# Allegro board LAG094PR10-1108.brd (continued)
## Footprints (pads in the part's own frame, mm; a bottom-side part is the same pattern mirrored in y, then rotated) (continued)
ACES_50673-0120N-001_12P-T
  oval 0.61x1.499 smd: 1(0,0) 3(-1,0) 5(-2,0) 7(-3,0) 9(-4,0) 11(-5,0) 13(-6,0) 15(-7,0) 17(-8,0) 19(-9,0) 21(-10,0) 23(-11,0)
  oval 0.61x1.194 smd: 2(0,2.85) 4(-1,2.85) 6(-2,2.85) 8(-3,2.85) 10(-4,2.85) 12(-5,2.85) 14(-6,2.85) 16(-7,2.85) 18(-8,2.85) 20(-9,2.85) 22(-10,2.85) 24(-11,2.85)
  rect 1.702x2.311 smd: 25(-13.25,1.425) 26(2.25,1.425)
ACES_51522-00801-001_8P
  oval 0.305x1.295 smd: 1(0,0) 2(0.5,0) 3(1,0) 4(1.5,0) 5(2,0) 6(2.5,0) 7(3,0) 8(3.5,0)
  rect 2.489x1.905 smd: 9(5.65,-3.3) 10(-2.15,-3.3)
ACES_51524-0080N-001_8P
  oval 0.61x1.295 smd: 1(0,0) 2(1,0) 3(2,0) 4(3,0) 5(4,0) 6(5,0) 7(6,0) 8(7,0)
  rect 2.489x2.21 smd: 9(10,-3.05) 10(-3,-3.05)
ACES_51524-0160N-001_16P
  oval 0.61x1.295 smd: 1(0,0) 2(1,0) 3(2,0) 4(3,0) 5(4,0) 6(5,0) 7(6,0) 8(7,0) 9(8,0) 10(9,0) 11(10,0) 12(11,0) 13(12,0) 14(13,0) 15(14,0) 16(15,0)
  rect 2.159x2.21 smd: 17(-2.825,-3.05) 18(17.825,-3.05)
ACES_51540-04001-P01_40P
  oval 0.305x1.092 smd: 1(0,0) 2(0.5,0) 3(1,0) 4(1.5,0) 5(2,0) 6(2.5,0) 7(3,0) 8(3.5,0) 9(4,0) 10(4.5,0) 11(5,0) 12(5.5,0) 13(6,0) 14(6.5,0) 15(7,0) 16(7.5,0) 17(8,0) 18(8.5,0) 19(9,0) 20(9.5,0) 21(10,0) 22(10.5,0) 23(11,0) 24(11.5,0) 25(12,0) 26(12.5,0) 27(13,0) 28(13.5,0) 29(14,0) 30(14.5,0) 31(15,0) 32(15.5,0) 33(16,0) 34(16.5,0) 35(17,0) 36(17.5,0) 37(18,0) 38(18.5,0) 39(19,0) 40(19.5,0)
  rect 0.787x2.489 smd: 41(21.2,-3.6) 42(-1.7,-3.6)
ACES_51575-00401-001_4P
  oval 0.406x0.838 smd: 1(0,0) 2(1,0) 3(2,0) 4(3,0)
  rect 0.787x2.007 smd: 5(-2.2,-3.175) 6(5.2,-3.175)
ACES_51625-01201-001_12P
  oval 0.305x1.092 smd: 1(0,0) 2(0.5,0) 3(1,0) 4(1.5,0) 5(2,0) 6(2.5,0) 7(3,0) 8(3.5,0) 9(4,0) 10(4.5,0) 11(5,0) 12(5.5,0)
  rect 0.991x2.489 smd: 13(-1.8,-3.6) 14(7.3,-3.6)
ACON_HMRF6-AK120C_19P-T
  round 0.813 hole 0.559: 1(0,0) 2(0.5,1.55) 3(1,0) 4(1.5,1.55) 5(2,0) 6(2.5,1.55) 7(3,0) 8(3.5,1.55) 9(4,0) 10(4.5,1.55) 11(5,0) 12(5.5,1.55) 13(6,0) 14(6.5,1.55) 15(7,0) 16(7.5,1.55) 17(8,0) 18(8.5,1.55) 19(9,0)
  oval 1.499x2.21 hole 0.889x1.6: 20(11.75,1.7) 21(13.65,-7.75) 22(-4.65,-6.5) 23(-2.75,1.7)
ACON_TARAN-9R1391_9P
  round 0.991 hole 0.711: 1(0,0) 2(-2.5,0) 3(-4.5,0) 4(-7,0) 5(-7.5,-1.5) 6(-5.5,-1.5) 7(-3.5,-1.5) 8(-1.5,-1.5) 9(0.5,-1.5)
  oval 1.397x3.2 hole 0.787x2.591: 10(-11.35,-2.38) 12(4.35,-2.38)
  oval 1.397x2.388 hole 0.787x1.803: 11(-11.35,-9.48) 13(4.35,-9.48)
ALC3204-CG_MQFN40_5X5
  oval 0.889x0.203 smd: 1(0,0) 2(0,-0.4) 3(0,-0.8) 4(0,-1.2) 5(0,-1.6) 6(0,-2) 7(0,-2.4) 8(0,-2.8) 9(0,-3.2) 10(0,-3.6) 21(5.1,-3.6) 22(5.1,-3.2) 23(5.1,-2.8) 24(5.1,-2.4) 25(5.1,-2) 26(5.1,-1.6) 27(5.1,-1.2) 28(5.1,-0.8) 29(5.1,-0.4) 30(5.1,0)
  oval 0.203x0.889 smd: 11(0.75,-4.35) 12(1.15,-4.35) 13(1.55,-4.35) 14(1.95,-4.35) 15(2.35,-4.35) 16(2.75,-4.35) 17(3.15,-4.35) 18(3.55,-4.35) 19(3.95,-4.35) 20(4.35,-4.35) 31(4.35,0.75) 32(3.95,0.75) 33(3.55,0.75) 34(3.15,0.75) 35(2.75,0.75) 36(2.35,0.75) 37(1.95,0.75) 38(1.55,0.75) 39(1.15,0.75) 40(0.75,0.75)
  rect 3.607x3.607 smd: 41(2.55,-1.8)
AON6380_DFN5X6-8-5
  oval 0.508x0.838 smd: 1(0,0) 2(1.27,0) 3(2.54,0) 4(3.81,0)
  custom 1.15x1.15 smd: 5(1.905,3.69)
AON7702L_DFN8-5
  oval 0.406x0.991 smd: 1(0,0) 2(0.66,0) 3(1.32,0) 4(1.98,0)
  custom 0.559x0.559 smd: 5(0.99,2.247)
AONH36334_DFN3X3A8-10
  oval 0.457x0.813 smd: 1(0,0) 2(0.65,0) 3(1.3,0) 4(1.95,0) 5(1.95,3.18) 6(1.3,3.18) 7(0.65,3.18) 8(0,3.18)
  rect 2.388x0.991 smd: 9(0.975,2.025)
  rect 2.388x0.508 smd: 10(0.975,0.92)
AP2302GN-HF_SOT23-3
  oval 1.016x1.524 smd: 1(0,0) 2(0.965,2.083) 3(-0.965,2.083)
AZ1045-04F_DFN2510P10E-10-9
  oval 0.254x0.686 smd: 1(0,0) 2(0.5,0) 4(1.5,0) 5(2,0) 6(2,0.875) 7(1.5,0.875) 8(0.5,0.875) 9(0,0.875)
  oval 0.381x1.549 smd: 3(1,0.437)
AZ5123-02SPR7G_SOT23-3
  oval 1.016x1.524 smd: 1(0,0) 2(0.965,2.083) 3(-0.965,2.083)
AZC199-02SPR7G_SOT23-3
  oval 1.016x1.524 smd: 1(0,0) 2(0.965,2.083) 3(-0.965,2.083)
BAS40C_SOT23-3
  oval 1.016x1.524 smd: 1(0,0) 2(0.965,2.083) 3(-0.965,2.083)
BAT54ATB_SOT523-3
  oval 0.406x0.457 smd: 1(0,0) 2(0.5,1.35) 3(-0.5,1.35)
BAT54C-7-F_SOT23-3
  oval 1.016x1.524 smd: 1(0,0) 2(0.965,2.083) 3(-0.965,2.083)
BAT54CW_SOT323-3
  oval 0.711x0.889 smd: 1(0,0) 2(-0.65,-1.9) 3(0.65,-1.9)
BAV99W_SC70-3
  oval 0.508x0.559 smd: 1(0,0) 2(-0.65,-1.85) 3(0.65,-1.85)
BAW56W_SOT323-3
  oval 0.813x0.914 smd: 1(0,0) 2(0.65,1.6) 3(-0.65,1.6)
BOTH_NS0013LF_16P
  oval 0.762x1.905 smd: 1(0,0) 2(1.27,0) 3(2.54,0) 4(3.81,0) 5(5.08,0) 6(6.35,0) 7(7.62,0) 8(8.89,0) 9(8.89,8.8) 10(7.62,8.8) 11(6.35,8.8) 12(5.08,8.8) 13(3.81,8.8) 14(2.54,8.8) 15(1.27,8.8) 16(0,8.8)
C_0201
  rect 0.381x0.356 smd: 1(0,0) 2(0.584,0)
C_0402
  rect 0.508x0.584 smd: 1(0,0) 2(0.914,0)
C_0603
  rect 0.635x0.889 smd: 1(0,0) 2(1.397,0)
C_0805
  rect 0.813x1.397 smd: 1(0,0) 2(1.702,0)
C_1206
  rect 1.016x1.778 smd: 1(0,0) 2(2.667,0)
C_A
  rect 1.626x1.829 smd: 1(0.389,0) 2(2.989,0)
C_B2
  rect 1.346x2.692 smd: 1(0,0) 2(-2.75,0)
C_D2
  rect 2.388x2.794 smd: 1(0,0) 2(6.4,0)
CH751H-40PT_SOD323-2
  rect 0.711x0.711 smd: 1(0,0) 2(2.33,0)
CK0402101V05_0402-2
  rect 0.508x0.559 smd: 1(0,0) 2(0.92,0)
DDTA144VCA-7-F_SOT23-3
  oval 1.016x1.524 smd: 1(0,0) 2(0.965,2.083) 3(-0.965,2.083)
DMN65D8LW-7_SOT323-3
  oval 0.711x0.889 smd: 1(0,0) 2(-0.65,-1.9) 3(0.65,-1.9)
DMN66D0LDW-7_SOT363-6
  oval 0.432x0.61 smd: 1(0,0) 2(0.65,0) 3(1.3,0) 4(1.3,1.9) 5(0.65,1.9) 6(0,1.9)
EMB04N03H_EDFN5X6-8-5
  oval 0.61x1.27 smd: 1(0,0) 2(1.27,0) 3(2.54,0) 4(3.81,0)
  custom 1.105x1.105 smd: 5(1.905,3.715)
F_1206L150PR
  rect 0.991x1.803 smd: 1(0,0) 2(2.8,0)
F_MF-NSMF050-2
  rect 0.991x1.6 smd: 1(0,0) 2(3,0)
F_SMD1812P150TF-24
  rect 1.778x3.15 smd: 1(0,0) 2(5.23,0)
F_T0603FF1000TM
  rect 0.711x0.991 smd: 1(0,0) 2(1.5,0)
FDV301N-G_SOT23-3
  oval 1.016x1.524 smd: 1(0,0) 2(0.965,2.083) 3(-0.965,2.083)
FH8068003067411-QM_FCBGA_1090P
  round 0.305 smd: A3(-0.784,0) A4(-1.381,0) A6(-1.978,0) A7(-2.752,0) A50(-21.403,0) A51(-22,0) A53(-22.609,0) A54(-23.219,0) AA5(-1.713,8.964) AA7(-2.424,8.964) AA8(-3.136,8.964) AA10(-3.847,8.964) AA12(-4.558,8.964) AA13(-5.269,8.964) AA15(-5.98,8.964) AA17(-6.692,8.964) AA39(-16.937,8.964) AA41(-17.648,8.964) AA43(-18.359,8.964) AA44(-19.071,8.964) AA46(-19.782,8.964) AA48(-20.493,8.964) AA49(-21.204,8.964) AA51(-21.915,8.964) AC5(-1.713,9.917) AC7(-2.424,9.917) AC8(-3.136,9.917) AC10(-3.847,9.917) AC12(-4.558,9.917) AC13(-5.269,9.917) AC15(-5.98,9.917) AC17(-6.692,9.917) AC39(-16.937,9.917) AC41(-17.648,9.917) AC43(-18.359,9.917) AC44(-19.071,9.917) AC46(-19.782,9.917) AC48(-20.493,9.917) AC49(-21.204,9.917) AC51(-21.915,9.917) AE5(-1.713,10.793) AE7(-2.424,10.793) AE8(-3.136,10.793) AE10(-3.847,10.793) AE12(-4.558,10.793) AE13(-5.269,10.793) AE15(-5.98,10.793) AE17(-6.692,10.793) AE39(-16.937,10.793) AE41(-17.648,10.793) AE43(-18.359,10.793) AE44(-19.071,10.793) AE46(-19.782,10.793) AE48(-20.493,10.793) AE49(-21.204,10.793) AE51(-21.915,10.793) AF6(-2.069,11.314) AF8(-2.78,11.314) AF9(-3.491,11.314) AF11(-4.202,11.314) AF12(-4.914,11.314) AF14(-5.625,11.314) AF16(-6.336,11.314) AF40(-17.293,11.314) AF42(-18.004,11.314) AF44(-18.715,11.314) AF45(-19.426,11.314) AF47(-20.137,11.314) AF48(-20.849,11.314) AF50(-21.56,11.314) AG5(-1.713,11.835) AG7(-2.424,11.835) AG8(-3.136,11.835) AG10(-3.847,11.835) AG12(-4.558,11.835) AG13(-5.269,11.835) AG15(-5.98,11.835) AG17(-6.692,11.835) AG39(-16.937,11.835) AG41(-17.648,11.835) AG43(-18.359,11.835) AG44(-19.071,11.835) AG46(-19.782,11.835) AG48(-20.493,11.835) AG49(-21.204,11.835) AG51(-21.915,11.835) AJ5(-1.713,12.711) AJ7(-2.424,12.711) AJ8(-3.136,12.711) AJ10(-3.847,12.711) AJ12(-4.558,12.711) AJ13(-5.269,12.711) AJ15(-5.98,12.711) AJ17(-6.692,12.711) AJ39(-16.937,12.711) AJ41(-17.648,12.711) AJ43(-18.359,12.711) AJ44(-19.071,12.711) AJ46(-19.782,12.711) AJ48(-20.493,12.711) AJ49(-21.204,12.711) AJ51(-21.915,12.711) AL5(-1.713,13.663) AL7(-2.424,13.663) AL8(-3.136,13.663) AL10(-3.847,13.663) AL12(-4.558,13.663) AL13(-5.269,13.663) AL15(-5.98,13.663) AL17(-6.692,13.663) AL39(-16.937,13.663) AL41(-17.648,13.663) AL43(-18.359,13.663) AL44(-19.071,13.663) AL46(-19.782,13.663) AL48(-20.493,13.663) AL49(-21.204,13.663) AL51(-21.915,13.663) AN5(-1.713,14.54) AN7(-2.424,14.54) AN8(-3.136,14.54) AN10(-3.847,14.54) AN12(-4.558,14.54) AN13(-5.269,14.54) AN15(-5.98,14.54) AN17(-6.692,14.54) AN39(-16.937,14.54) AN41(-17.648,14.54) AN43(-18.359,14.54) AN44(-19.071,14.54) AN46(-19.782,14.54) AN48(-20.493,14.54) AN49(-21.204,14.54) AN51(-21.915,14.54) AR5(-1.713,15.226) AR7(-2.424,15.226) AR8(-3.136,15.226) AR10(-3.847,15.226) AR12(-4.558,15.226) AR13(-5.269,15.226) AR15(-5.98,15.226) AR17(-6.692,15.226) AR39(-16.937,15.226) AR41(-17.648,15.226) AR43(-18.359,15.226) AR44(-19.071,15.226) AR46(-19.782,15.226) AR48(-20.493,15.226) AR49(-21.204,15.226) AR51(-21.915,15.226) AU5(-1.713,16.102) AU7(-2.424,16.102) AU8(-3.136,16.102) AU10(-3.847,16.102) AU12(-4.558,16.102) AU13(-5.269,16.102) AU15(-5.98,16.102) AU28(-11.814,16.292) AU41(-17.648,16.102) AU43(-18.359,16.102) AU44(-19.071,16.102) AU46(-19.782,16.102) AU48(-20.493,16.102) AU49(-21.204,16.102) AU51(-21.915,16.102) AV15(-6.15,16.647) AV17(-7.026,16.647) AV19(-7.903,16.647) AV21(-8.589,16.647) AV23(-9.465,16.647) AV25(-10.417,16.647) AV27(-11.294,16.647) AV29(-12.335,16.647) AV31(-13.211,16.647) AV33(-14.164,16.647) AV35(-15.04,16.647) AV37(-15.726,16.647) AV39(-16.602,16.647) AV41(-17.479,16.647) AW5(-1.713,17.054) AW7(-2.424,17.054) AW8(-3.136,17.054) AW10(-3.847,17.054) AW12(-4.558,17.054) AW28(-11.814,17.003) AW44(-19.071,17.054) AW46(-19.782,17.054) AW48(-20.493,17.054) AW49(-21.204,17.054) AW51(-21.915,17.054) AY13(-5.121,17.359) AY15(-6.074,17.359) AY17(-7.026,17.359) AY19(-7.903,17.359) AY21(-8.589,17.359) AY23(-9.465,17.359) AY25(-10.417,17.359) AY27(-11.294,17.359) AY28(-11.814,17.714) AY29(-12.335,17.359) AY31(-13.211,17.359) AY33(-14.164,17.359) AY35(-15.04,17.359) AY37(-15.726,17.359) AY39(-16.602,17.359) AY41(-17.555,17.359) AY43(-18.507,17.359) B2(-0.38,0.38) B55(-23.629,0.44) BA5(-1.713,18.007) BA7(-2.424,18.007) BA8(-3.136,18.007) BA10(-3.847,18.007) BA13(-5.121,18.07) BA15(-6.074,18.07) BA17(-7.026,18.07) BA19(-7.903,18.07) BA21(-8.589,18.07) BA23(-9.465,18.07) BA25(-10.417,18.07) BA27(-11.294,18.07) BA29(-12.335,18.07) BA31(-13.211,18.07) BA33(-14.164,18.07) BA35(-15.04,18.07) BA37(-15.726,18.07) BA39(-16.602,18.07) BA41(-17.555,18.07) BA43(-18.507,18.07) BA46(-19.782,18.007) BA48(-20.493,18.007) BA49(-21.204,18.007) BA51(-21.915,18.007) BB28(-11.814,18.425) BC5(-1.713,18.959) BC7(-2.424,18.959) BC8(-3.136,18.959) BC11(-4.169,18.781) BC13(-5.121,18.781) BC15(-6.074,18.781) BC17(-7.026,18.781) BC19(-7.903,18.781) BC21(-8.589,18.781) BC23(-9.465,18.781) BC25(-10.417,18.781) BC27(-11.294,18.781) BC29(-12.335,18.781) BC31(-13.211,18.781) BC33(-14.164,18.781) BC35(-15.04,18.781) BC37(-15.726,18.781) BC39(-16.602,18.781) BC41(-17.555,18.781) BC43(-18.507,18.781) BC45(-19.46,18.781) BC48(-20.493,18.959) BC49(-21.204,18.959) BC51(-21.915,18.959) BD9(-3.293,19.492) BD11(-4.169,19.492) BD13(-5.121,19.492) BD15(-6.074,19.492) BD17(-7.026,19.492) BD19(-7.903,19.492) BD21(-8.589,19.492) BD23(-9.465,19.492) BD25(-10.417,19.492) BD27(-11.294,19.492) BD28(-11.814,19.137) BD29(-12.335,19.492) BD31(-13.211,19.492) BD33(-14.164,19.492) BD35(-15.04,19.492) BD37(-15.726,19.492) BD39(-16.602,19.492) BD41(-17.555,19.492) BD43(-18.507,19.492) BD45(-19.46,19.492) BD47(-20.336,19.492) BE5(-1.713,19.912) BE7(-2.424,19.912) BE28(-11.814,19.848) BE49(-21.204,19.912) BE51(-21.915,19.912) BF1(0,20.371) BF2(-0.551,20.439) BF9(-3.216,20.203) BF11(-4.169,20.203) BF13(-5.121,20.203) BF15(-6.074,20.203) BF17(-7.026,20.203) BF19(-7.903,20.203) BF21(-8.589,20.203) BF23(-9.465,20.203) BF25(-10.417,20.203) BF27(-11.294,20.203) BF29(-12.335,20.203) BF31(-13.211,20.203) BF33(-14.164,20.203) BF35(-15.04,20.203) BF37(-15.726,20.203) BF39(-16.602,20.203) BF41(-17.555,20.203) BF43(-18.507,20.203) BF45(-19.46,20.203) BF47(-20.412,20.203) BF54(-23.078,20.439) BF55(-23.629,20.371) BG1(0,20.968) BG2(-0.551,20.985) BG4(-1.138,21.011) BG6(-2.264,20.915) BG28(-11.814,20.559) BG50(-21.365,20.915) BG52(-22.49,21.011) BG54(-23.078,20.985) BG55(-23.629,20.968) BH1(0,21.578) BH2(-0.551,21.531) BH5(-1.709,21.529) BH6(-2.261,21.531) BH9(-3.216,20.915) BH11(-4.169,20.915) BH13(-5.121,20.915) BH15(-6.074,20.915) BH17(-7.026,20.915) BH19(-7.903,20.915) BH21(-8.589,20.915) BH23(-9.465,20.915) BH25(-10.417,20.915) BH27(-11.294,20.915) BH29(-12.335,20.915) BH31(-13.211,20.915) BH33(-14.164,20.915) BH35(-15.04,20.915) BH37(-15.726,20.915) BH39(-16.602,20.915) BH41(-17.555,20.915) BH43(-18.507,20.915) BH45(-19.46,20.915) BH47(-20.412,20.915) BH50(-21.367,21.531) BH51(-21.919,21.529) BH54(-23.078,21.531) BH55(-23.629,21.578) BJ2(-0.551,22.077) BJ4(-1.097,22.077) BJ5(-1.643,22.077) BJ6(-2.189,22.077) BJ50(-21.439,22.077) BJ51(-21.985,22.077) BJ52(-22.532,22.077) BJ54(-23.078,22.077) BK1(0,22.187) BK55(-23.629,22.187) BL2(-0.41,22.628) BL3(-1.019,22.628) BL5(-1.629,22.628) BL6(-2.226,22.628) BL50(-21.403,22.628) BL51(-22,22.628) BL53(-22.609,22.628) BL54(-23.219,22.628) C1(0,0.784) C2(-0.551,0.945) C3(-0.945,0.551) C5(-1.491,0.551) C6(-2.037,0.551) C7(-2.583,0.551) C50(-21.439,0.551) C51(-21.985,0.551) C52(-22.532,0.551) C54(-23.078,0.551) D1(0,1.381) D2(-0.551,1.491) D4(-1.122,1.097) D6(-2.164,1.084) D9(-3.293,1.713) D11(-4.169,1.713) D13(-5.121,1.713) D15(-6.074,1.713) D17(-7.026,1.713) D19(-7.903,1.713) D21(-8.589,1.713) D23(-9.465,1.713) D25(-10.417,1.713) D27(-11.294,1.713) D29(-12.335,1.713) D31(-13.211,1.713) D33(-14.164,1.713) D35(-15.04,1.713) D37(-15.726,1.713) D39(-16.602,1.713) D41(-17.555,1.713) D43(-18.507,1.713) D45(-19.46,1.713) D47(-20.412,1.713) D50(-21.367,1.097) D51(-21.919,1.099) D54(-23.078,1.097) D55(-23.629,1.05) E2(-0.551,2.037) E5(-1.656,1.592) E7(-2.74,1.618) E28(-11.814,2.069) E50(-21.365,1.713) E52(-22.49,1.616) E54(-23.078,1.643) E55(-23.629,1.66) F1(0,1.978) F2(-0.551,2.583) F4(-1.122,2.113) F6(-2.164,2.1) F9(-3.293,2.424) F11(-4.169,2.424) F13(-5.121,2.424) F15(-6.074,2.424) F17(-7.026,2.424) F19(-7.903,2.424) F21(-8.589,2.424) F23(-9.465,2.424) F25(-10.417,2.424) F27(-11.294,2.424) F29(-12.335,2.424) F31(-13.211,2.424) F33(-14.164,2.424) F35(-15.04,2.424) F37(-15.726,2.424) F39(-16.602,2.424) F41(-17.555,2.424) F43(-18.507,2.424) F45(-19.46,2.424) F47(-20.412,2.424) F54(-23.078,2.189) F55(-23.629,2.257) G5(-1.656,2.634) G7(-2.74,2.634) G28(-11.814,2.78) G49(-21.204,2.716) G51(-21.915,2.716) H1(0,2.752) H4(-1.122,3.129) H6(-2.164,3.116) H9(-3.293,3.136) H11(-4.169,3.136) H13(-5.121,3.136) H15(-6.074,3.136) H17(-7.026,3.136) H19(-7.903,3.136) H21(-8.589,3.136) H23(-9.465,3.136) H25(-10.417,3.136) H27(-11.294,3.136) H28(-11.814,3.491) H29(-12.335,3.136) H31(-13.211,3.136) H33(-14.164,3.136) H35(-15.04,3.136) H37(-15.726,3.136) H39(-16.602,3.136) H41(-17.555,3.136) H43(-18.507,3.136) H45(-19.46,3.136) H47(-20.336,3.136) J5(-1.713,3.745) J7(-2.424,3.745) J8(-3.136,3.745) J11(-4.169,3.847) J13(-5.121,3.847) J15(-6.074,3.847) J17(-7.026,3.847) J19(-7.903,3.847) J21(-8.589,3.847) J23(-9.465,3.847) J25(-10.417,3.847) J27(-11.294,3.847) J29(-12.335,3.847) J31(-13.211,3.847) J33(-14.164,3.847) J35(-15.04,3.847) J37(-15.726,3.847) J39(-16.602,3.847) J41(-17.555,3.847) J43(-18.507,3.847) J45(-19.46,3.847) J48(-20.493,3.669) J49(-21.204,3.669) J51(-21.915,3.669) K28(-11.814,4.202) L5(-1.713,4.621) L7(-2.424,4.621) L8(-3.136,4.621) L10(-3.847,4.621) L13(-5.121,4.558) L15(-6.074,4.558) L17(-7.026,4.558) L19(-7.903,4.558) L21(-8.589,4.558) L23(-9.465,4.558) L25(-10.417,4.558) L27(-11.294,4.558) L29(-12.335,4.558) L31(-13.211,4.558) L33(-14.164,4.558) L35(-15.04,4.558) L37(-15.726,4.558) L39(-16.602,4.558) L41(-17.555,4.558) L43(-18.507,4.558) L46(-19.782,4.621) L48(-20.493,4.621) L49(-21.204,4.621) L51(-21.915,4.621) M13(-5.121,5.269) M15(-6.074,5.269) M17(-7.026,5.269) M19(-7.903,5.269) M21(-8.589,5.269) M23(-9.465,5.269) M25(-10.417,5.269) M27(-11.294,5.269) M28(-11.814,4.914) M29(-12.335,5.269) M31(-13.211,5.269) M33(-14.164,5.269) M35(-15.04,5.269) M37(-15.726,5.269) M39(-16.602,5.269) M41(-17.555,5.269) M43(-18.507,5.269) N5(-1.713,5.574) N7(-2.424,5.574) N8(-3.136,5.574) N10(-3.847,5.574) N12(-4.558,5.574) N28(-11.814,5.625) N44(-19.071,5.574) N46(-19.782,5.574) N48(-20.493,5.574) N49(-21.204,5.574) N51(-21.915,5.574) P15(-6.15,5.98) P17(-7.026,5.98) P19(-7.903,5.98) P21(-8.589,5.98) P23(-9.465,5.98) P25(-10.417,5.98) P27(-11.294,5.98) P29(-12.335,5.98) P31(-13.211,5.98) P33(-14.164,5.98) P35(-15.04,5.98) P37(-15.726,5.98) P39(-16.602,5.98) P41(-17.479,5.98) R5(-1.713,6.526) R7(-2.424,6.526) R8(-3.136,6.526) R10(-3.847,6.526) R12(-4.558,6.526) R13(-5.269,6.526) R15(-5.98,6.526) R28(-11.814,6.336) R41(-17.648,6.526) R43(-18.359,6.526) R44(-19.071,6.526) R46(-19.782,6.526) R48(-20.493,6.526) R49(-21.204,6.526) R51(-21.915,6.526) U5(-1.713,7.402) U7(-2.424,7.402) U8(-3.136,7.402) U10(-3.847,7.402) U12(-4.558,7.402) U13(-5.269,7.402) U15(-5.98,7.402) U17(-6.692,7.402) U39(-16.937,7.402) U41(-17.648,7.402) U43(-18.359,7.402) U44(-19.071,7.402) U46(-19.782,7.402) U48(-20.493,7.402) U49(-21.204,7.402) U51(-21.915,7.402) W5(-1.713,8.088) W7(-2.424,8.088) W8(-3.136,8.088) W10(-3.847,8.088) W12(-4.558,8.088) W13(-5.269,8.088) W15(-5.98,8.088) W17(-6.692,8.088) W39(-16.937,8.088) W41(-17.648,8.088) W43(-18.359,8.088) W44(-19.071,8.088) W46(-19.782,8.088) W48(-20.493,8.088) W49(-21.204,8.088) W51(-21.915,8.088)
  round 0.254 smd: A10(-3.699,0) A12(-4.601,0) A14(-5.502,0) A16(-6.404,0) A18(-7.306,0) A20(-8.208,0) A22(-9.109,0) A24(-10.011,0) A26(-10.913,0) A28(-11.814,0) A30(-12.716,0) A32(-13.618,0) A34(-14.519,0) A36(-15.421,0) A38(-16.323,0) A40(-17.225,0) A42(-18.126,0) A44(-19.028,0) A46(-19.93,0) A48(-20.831,0) AA2(-0.311,9.06) AA3(-0.934,9.06) AA53(-22.694,9.06) AA54(-23.317,9.06) AB1(0,9.511) AB3(-0.623,9.511) AB53(-23.006,9.511) AB55(-23.629,9.511) AC2(-0.311,9.961) AC3(-0.934,9.961) AC53(-22.694,9.961) AC54(-23.317,9.961) AD1(0,10.412) AD3(-0.623,10.412) AD53(-23.006,10.412) AD55(-23.629,10.412) AE2(-0.311,10.863) AE3(-0.934,10.863) AE53(-22.694,10.863) AE54(-23.317,10.863) AF1(0,11.314) AF3(-0.623,11.314) AF4(-1.246,11.314) AF52(-22.383,11.314) AF53(-23.006,11.314) AF55(-23.629,11.314) AG2(-0.311,11.765) AG3(-0.934,11.765) AG53(-22.694,11.765) AG54(-23.317,11.765) AH1(0,12.216) AH3(-0.623,12.216) AH53(-23.006,12.216) AH55(-23.629,12.216) AJ2(-0.311,12.666) AJ3(-0.934,12.666) AJ53(-22.694,12.666) AJ54(-23.317,12.666) AK1(0,13.117) AK3(-0.623,13.117) AK53(-23.006,13.117) AK55(-23.629,13.117) AL2(-0.311,13.568) AL3(-0.934,13.568) AL53(-22.694,13.568) AL54(-23.317,13.568) AM1(0,14.019) AM3(-0.623,14.019) AM53(-23.006,14.019) AM55(-23.629,14.019) AN2(-0.311,14.47) AN3(-0.934,14.47) AN53(-22.694,14.47) AN54(-23.317,14.47) AP1(0,14.921) AP3(-0.623,14.921) AP53(-23.006,14.921) AP55(-23.629,14.921) AR2(-0.311,15.372) AR3(-0.934,15.372) AR53(-22.694,15.372) AR54(-23.317,15.372) AT1(0,15.822) AT3(-0.623,15.822) AT53(-23.006,15.822) AT55(-23.629,15.822) AU2(-0.311,16.273) AU3(-0.934,16.273) AU53(-22.694,16.273) AU54(-23.317,16.273) AV1(0,16.724) AV3(-0.623,16.724) AV53(-23.006,16.724) AV55(-23.629,16.724) AW2(-0.311,17.175) AW3(-0.934,17.175) AW53(-22.694,17.175) AW54(-23.317,17.175) AY1(0,17.626) AY3(-0.623,17.626) AY53(-23.006,17.626) AY55(-23.629,17.626) B9(-3.248,0.311) B11(-4.15,0.311) B13(-5.052,0.311) B15(-5.953,0.311) B17(-6.855,0.311) B19(-7.757,0.311) B21(-8.658,0.311) B23(-9.56,0.311) B25(-10.462,0.311) B27(-11.363,0.311) B29(-12.265,0.311) B31(-13.167,0.311) B33(-14.069,0.311) B35(-14.97,0.311) B37(-15.872,0.311) B39(-16.774,0.311) B41(-17.675,0.311) B43(-18.577,0.311) B45(-19.479,0.311) B47(-20.38,0.311) BA2(-0.311,18.077) BA3(-0.934,18.077) BA53(-22.694,18.077) BA54(-23.317,18.077) BB1(0,18.528) BB3(-0.623,18.528) BB53(-23.006,18.528) BB55(-23.629,18.528) BC2(-0.311,18.978) BC3(-0.934,18.978) BC53(-22.694,18.978) BC54(-23.317,18.978) BD1(0,19.429) BD3(-0.623,19.429) BD53(-23.006,19.429) BD55(-23.629,19.429) BE2(-0.311,19.88) BE3(-0.934,19.88) BE53(-22.694,19.88) BE54(-23.317,19.88) BH28(-11.814,21.382) BJ8(-2.797,22.005) BJ9(-3.248,21.694) BJ10(-3.699,22.005) BJ11(-4.15,21.694) BJ12(-4.601,22.005) BJ13(-5.052,21.694) BJ14(-5.502,22.005) BJ15(-5.953,21.694) BJ16(-6.404,22.005) BJ17(-6.855,21.694) BJ18(-7.306,22.005) BJ19(-7.757,21.694) BJ20(-8.208,22.005) BJ21(-8.658,21.694) BJ22(-9.109,22.005) BJ23(-9.56,21.694) BJ24(-10.011,22.005) BJ25(-10.462,21.694) BJ26(-10.913,22.005) BJ27(-11.363,21.694) BJ28(-11.814,22.005) BJ29(-12.265,21.694) BJ30(-12.716,22.005) BJ31(-13.167,21.694) BJ32(-13.618,22.005) BJ33(-14.069,21.694) BJ34(-14.519,22.005) BJ35(-14.97,21.694) BJ36(-15.421,22.005) BJ37(-15.872,21.694) BJ38(-16.323,22.005) BJ39(-16.774,21.694) BJ40(-17.225,22.005) BJ41(-17.675,21.694) BJ42(-18.126,22.005) BJ43(-18.577,21.694) BJ44(-19.028,22.005) BJ45(-19.479,21.694) BJ46(-19.93,22.005) BJ47(-20.38,21.694) BJ48(-20.831,22.005) BK9(-3.248,22.316) BK11(-4.15,22.316) BK13(-5.052,22.316) BK15(-5.953,22.316) BK17(-6.855,22.316) BK19(-7.757,22.316) BK21(-8.658,22.316) BK23(-9.56,22.316) BK25(-10.462,22.316) BK27(-11.363,22.316) BK29(-12.265,22.316) BK31(-13.167,22.316) BK33(-14.069,22.316) BK35(-14.97,22.316) BK37(-15.872,22.316) BK39(-16.774,22.316) BK41(-17.675,22.316) BK43(-18.577,22.316) BK45(-19.479,22.316) BK47(-20.38,22.316) BL8(-2.797,22.628) BL10(-3.699,22.628) BL12(-4.601,22.628) BL14(-5.502,22.628) BL16(-6.404,22.628) BL18(-7.306,22.628) BL20(-8.208,22.628) BL22(-9.109,22.628) BL24(-10.011,22.628) BL26(-10.913,22.628) BL28(-11.814,22.628) BL30(-12.716,22.628) BL32(-13.618,22.628) BL34(-14.519,22.628) BL36(-15.421,22.628) BL38(-16.323,22.628) BL40(-17.225,22.628) BL42(-18.126,22.628) BL44(-19.028,22.628) BL46(-19.93,22.628) BL48(-20.831,22.628) C9(-3.248,0.934) C10(-3.699,0.623) C11(-4.15,0.934) C12(-4.601,0.623) C13(-5.052,0.934) C14(-5.502,0.623) C15(-5.953,0.934) C16(-6.404,0.623) C17(-6.855,0.934) C18(-7.306,0.623) C19(-7.757,0.934) C20(-8.208,0.623) C21(-8.658,0.934) C22(-9.109,0.623) C23(-9.56,0.934) C24(-10.011,0.623) C25(-10.462,0.934) C26(-10.913,0.623) C27(-11.363,0.934) C28(-11.814,0.623) C29(-12.265,0.934) C30(-12.716,0.623) C31(-13.167,0.934) C32(-13.618,0.623) C33(-14.069,0.934) C34(-14.519,0.623) C35(-14.97,0.934) C36(-15.421,0.623) C37(-15.872,0.934) C38(-16.323,0.623) C39(-16.774,0.934) C40(-17.225,0.623) C41(-17.675,0.934) C42(-18.126,0.623) C43(-18.577,0.934) C44(-19.028,0.623) C45(-19.479,0.934) C46(-19.93,0.623) C47(-20.38,0.934) C48(-20.831,0.623) D28(-11.814,1.246) G53(-22.694,2.748) G54(-23.317,2.748) H2(-0.568,3.162) H53(-23.006,3.199) H55(-23.629,3.199) J2(-0.311,3.649) J3(-0.934,3.649) J53(-22.694,3.649) J54(-23.317,3.649) K1(0,4.1) K3(-0.623,4.1) K53(-23.006,4.1) K55(-23.629,4.1) L2(-0.311,4.551) L3(-0.934,4.551) L53(-22.694,4.551) L54(-23.317,4.551) M1(0,5.002) M3(-0.623,5.002) M53(-23.006,5.002) M55(-23.629,5.002) N2(-0.311,5.453) N3(-0.934,5.453) N53(-22.694,5.453) N54(-23.317,5.453) P1(0,5.904) P3(-0.623,5.904) P53(-23.006,5.904) P55(-23.629,5.904) R2(-0.311,6.355) R3(-0.934,6.355) R53(-22.694,6.355) R54(-23.317,6.355) T1(0,6.805) T3(-0.623,6.805) T53(-23.006,6.805) T55(-23.629,6.805) U2(-0.311,7.256) U3(-0.934,7.256) U53(-22.694,7.256) U54(-23.317,7.256) V1(0,7.707) V3(-0.623,7.707) V53(-23.006,7.707) V55(-23.629,7.707) W2(-0.311,8.158) W3(-0.934,8.158) W53(-22.694,8.158) W54(-23.317,8.158) Y1(0,8.609) Y3(-0.623,8.609) Y53(-23.006,8.609) Y55(-23.629,8.609)
  round 0.33 smd: AA18(-7.242,9.142) AA20(-8.004,9.142) AA21(-8.766,9.142) AA23(-9.528,9.142) AA25(-10.29,9.142) AA27(-11.052,9.142) AA28(-11.814,9.142) AA29(-12.576,9.142) AA31(-13.338,9.142) AA33(-14.1,9.142) AA35(-14.862,9.142) AA36(-15.624,9.142) AA38(-16.386,9.142) AC18(-7.242,9.866) AC20(-8.004,9.866) AC21(-8.766,9.866) AC23(-9.528,9.866) AC25(-10.29,9.866) AC27(-11.052,9.866) AC28(-11.814,9.866) AC29(-12.576,9.866) AC31(-13.338,9.866) AC33(-14.1,9.866) AC35(-14.862,9.866) AC36(-15.624,9.866) AC38(-16.386,9.866) AE18(-7.242,10.59) AE20(-8.004,10.59) AE21(-8.766,10.59) AE23(-9.528,10.59) AE25(-10.29,10.59) AE27(-11.052,10.59) AE28(-11.814,10.59) AE29(-12.576,10.59) AE31(-13.338,10.59) AE33(-14.1,10.59) AE35(-14.862,10.59) AE36(-15.624,10.59) AE38(-16.386,10.59) AF18(-7.242,11.314) AF20(-8.004,11.314) AF21(-8.766,11.314) AF23(-9.528,11.314) AF25(-10.29,11.314) AF27(-11.052,11.314) AF28(-11.814,11.314) AF29(-12.576,11.314) AF31(-13.338,11.314) AF33(-14.1,11.314) AF35(-14.862,11.314) AF36(-15.624,11.314) AF38(-16.386,11.314) AG18(-7.242,12.038) AG20(-8.004,12.038) AG21(-8.766,12.038) AG23(-9.528,12.038) AG25(-10.29,12.038) AG27(-11.052,12.038) AG28(-11.814,12.038) AG29(-12.576,12.038) AG31(-13.338,12.038) AG33(-14.1,12.038) AG35(-14.862,12.038) AG36(-15.624,12.038) AG38(-16.386,12.038) AJ18(-7.242,12.762) AJ20(-8.004,12.762) AJ21(-8.766,12.762) AJ23(-9.528,12.762) AJ25(-10.29,12.762) AJ27(-11.052,12.762) AJ28(-11.814,12.762) AJ29(-12.576,12.762) AJ31(-13.338,12.762) AJ33(-14.1,12.762) AJ35(-14.862,12.762) AJ36(-15.624,12.762) AJ38(-16.386,12.762) AL18(-7.242,13.486) AL20(-8.004,13.486) AL21(-8.766,13.486) AL23(-9.528,13.486) AL25(-10.29,13.486) AL27(-11.052,13.486) AL28(-11.814,13.486) AL29(-12.576,13.486) AL31(-13.338,13.486) AL33(-14.1,13.486) AL35(-14.862,13.486) AL36(-15.624,13.486) AL38(-16.386,13.486) AM18(-7.242,14.21) AM20(-8.004,14.21) AM21(-8.766,14.21) AM23(-9.528,14.21) AM25(-10.29,14.21) AM27(-11.052,14.21) AM28(-11.814,14.21) AM29(-12.576,14.21) AM31(-13.338,14.21) AM33(-14.1,14.21) AM35(-14.862,14.21) AM36(-15.624,14.21) AM38(-16.386,14.21) AP18(-7.242,14.933) AP20(-8.004,14.933) AP21(-8.766,14.933) AP23(-9.528,14.933) AP25(-10.29,14.933) AP27(-11.052,14.933) AP28(-11.814,14.933) AP29(-12.576,14.933) AP31(-13.338,14.933) AP33(-14.1,14.933) AP35(-14.862,14.933) AP36(-15.624,14.933) AP38(-16.386,14.933) AT18(-7.242,15.657) AT20(-8.004,15.657) AT21(-8.766,15.657) AT23(-9.528,15.657) AT25(-10.29,15.657) AT27(-11.052,15.657) AT28(-11.814,15.657) AT29(-12.576,15.657) AT31(-13.338,15.657) AT33(-14.1,15.657) AT35(-14.862,15.657) AT36(-15.624,15.657) AT38(-16.386,15.657) T18(-7.242,6.971) T20(-8.004,6.971) T21(-8.766,6.971) T23(-9.528,6.971) T25(-10.29,6.971) T27(-11.052,6.971) T28(-11.814,6.971) T29(-12.576,6.971) T31(-13.338,6.971) T33(-14.1,6.971) T35(-14.862,6.971) T36(-15.624,6.971) T38(-16.386,6.971) V18(-7.242,7.694) V20(-8.004,7.694) V21(-8.766,7.694) V23(-9.528,7.694) V25(-10.29,7.694) V27(-11.052,7.694) V28(-11.814,7.694) V29(-12.576,7.694) V31(-13.338,7.694) V33(-14.1,7.694) V35(-14.862,7.694) V36(-15.624,7.694) V38(-16.386,7.694) Y18(-7.242,8.418) Y20(-8.004,8.418) Y21(-8.766,8.418) Y23(-9.528,8.418) Y25(-10.29,8.418) Y27(-11.052,8.418) Y28(-11.814,8.418) Y29(-12.576,8.418) Y31(-13.338,8.418) Y33(-14.1,8.418) Y35(-14.862,8.418) Y36(-15.624,8.418) Y38(-16.386,8.418)
FIDUCIAL_C40M80
  round 1.016 smd: 1(0,0)
GD25LB128CSIGR_SO8
  oval 0.635x1.676 smd: 1(0,0) 2(1.27,0) 3(2.54,0) 4(3.81,0) 5(3.81,7.23) 6(2.54,7.23) 7(1.27,7.23) 8(0,7.23)
H_3P0
  round 3.505 hole 2.997: 1(0,0)
H_3P0-G
  round 3.505 hole 2.997: 1(0,0)
H_3P0X4P0
  oval 3.505x4.496 hole 2.997x3.988: 1(0,0)
H_3P2
  round 3.708 hole 3.2: 1(0,0)
H_3P3
  round 3.81 hole 3.302: 1(0,0)
H_3P9
  round 4.42 hole 3.912: 1(0,0)
H_5P6N
  round 5.588 hole 5.588 unplated: (0,0)
HEFEN_AFB02-S30F1A-HF_30P-T
  oval 0.229x1.092 smd: 1(0,0) 2(-0.8,0) 3(-1.6,0) 4(-2.4,0) 5(-3.2,0) 6(-4,0) 7(-4.8,0) 8(-5.6,0) 9(-6.4,0) 10(-7.2,0) 11(-8,0) 12(-8.8,0) 13(-9.6,0) 14(-10.4,0) 15(-11.2,0) 16(-12,0) 17(-12.8,0) 18(-13.6,0) 19(-14.4,0) 20(-15.2,0) 21(-16,0) 22(-16.8,0) 23(-17.6,0) 24(-18.4,0) 25(-19.2,0) 26(-20,0) 27(-20.8,0) 28(-21.6,0) 29(-22.4,0) 30(-23.2,0)
  rect 0.559x1.295 smd: 31(1.475,-3.45) 32(-24.675,-3.45)
HRS_BM20B-20DS-0P4V_20P-T
  oval 0.203x0.432 smd: 1(0,0) 2(0,-2.18) 3(0.4,0) 4(0.4,-2.18) 5(0.8,0) 6(0.8,-2.18) 7(1.2,0) 8(1.2,-2.18) 9(1.6,0) 10(1.6,-2.18) 11(2,0) 12(2,-2.18) 13(2.4,0) 14(2.4,-2.18) 15(2.8,0) 16(2.8,-2.18) 17(3.2,0) 18(3.2,-2.18) 19(3.6,0) 20(3.6,-2.18)
  rect 0.305x0.762 smd: 21(-1.21,-0.165) 22(-1.21,-2.015) 23(4.81,-0.165) 24(4.81,-2.015)
INPAQ_HCM1012GH900BP_4P-NPM
  rect 0.711x0.305 smd: 1(0,0) 2(1.25,0) 3(1.25,-0.5) 4(0,-0.5)
INPAQ_MCM1012B900F06BP_4P
  rect 0.711x0.305 smd: 1(0,0) 2(1.25,0) 3(1.25,-0.5) 4(0,-0.5)
INPAQ_MCM1012B900F06BP_4P-NPM
  rect 0.711x0.305 smd: 1(0,0) 2(1.25,0) 3(1.25,-0.5) 4(0,-0.5)
ISL95522HRZ-T_TQFN32_4X4
  oval 0.889x0.203 smd: 1(0,0) 2(0,-0.4) 3(0,-0.8) 4(0,-1.2) 5(0,-1.6) 6(0,-2) 7(0,-2.4) 8(0,-2.8) 17(4.1,-2.8) 18(4.1,-2.4) 19(4.1,-2) 20(4.1,-1.6) 21(4.1,-1.2) 22(4.1,-0.8) 23(4.1,-0.4) 24(4.1,0)
  oval 0.203x0.889 smd: 9(0.65,-3.45) 10(1.05,-3.45) 11(1.45,-3.45) 12(1.85,-3.45) 13(2.25,-3.45) 14(2.65,-3.45) 15(3.05,-3.45) 16(3.45,-3.45) 25(3.45,0.65) 26(3.05,0.65) 27(2.65,0.65) 28(2.25,0.65) 29(1.85,0.65) 30(1.45,0.65) 31(1.05,0.65) 32(0.65,0.65)
  rect 2.642x2.642 smd: 33(2.05,-1.4)
JUMP_43X39
  custom 0.191x0.191 smd: 1(0,0) 2(0.914,0)
JUMP_43X39-NPM
  custom 0.191x0.191 smd: 1(0,0) 2(0.914,0)
JUMP_43X79
  custom 0.188x0.188 smd: 1(0,0) 2(1.1,0)
JUMP_43X79-NPM
  custom 0.188x0.188 smd: 1(0,0) 2(1.1,0)
JUMP_43X118
  custom 0.187x0.187 smd: 1(0,0) 2(1.1,0)
JUMP_43X118-NPM
  custom 0.187x0.187 smd: 1(0,0) 2(1.1,0)
JXT_FP226H-004S1AM_4P
  oval 0.61x1.295 smd: 1(0,0) 2(1,0) 3(2,0) 4(3,0)
  rect 0.991x2.007 smd: 5(-2.6,-3.25) 6(5.6,-3.25)
KB9542Q-B_LQFP128_14X14
  oval 1.803x0.254 smd: 1(0,0) 2(0,-0.4) 3(0,-0.8) 4(0,-1.2) 5(0,-1.6) 6(0,-2) 7(0,-2.4) 8(0,-2.8) 9(0,-3.2) 10(0,-3.6) 11(0,-4) 12(0,-4.4) 13(0,-4.8) 14(0,-5.2) 15(0,-5.6) 16(0,-6) 17(0,-6.4) 18(0,-6.8) 19(0,-7.2) 20(0,-7.6) 21(0,-8) 22(0,-8.4) 23(0,-8.8) 24(0,-9.2) 25(0,-9.6) 26(0,-10) 27(0,-10.4) 28(0,-10.8) 29(0,-11.2) 30(0,-11.6) 31(0,-12) 32(0,-12.4) 65(15.654,-12.4) 66(15.654,-12) 67(15.654,-11.6) 68(15.654,-11.2) 69(15.654,-10.8) 70(15.654,-10.4) 71(15.654,-10) 72(15.654,-9.6) 73(15.654,-9.2) 74(15.654,-8.8) 75(15.654,-8.4) 76(15.654,-8) 77(15.654,-7.6) 78(15.654,-7.2) 79(15.654,-6.8) 80(15.654,-6.4) 81(15.654,-6) 82(15.654,-5.6) 83(15.654,-5.2) 84(15.654,-4.8) 85(15.654,-4.4) 86(15.654,-4) 87(15.654,-3.6) 88(15.654,-3.2) 89(15.654,-2.8) 90(15.654,-2.4) 91(15.654,-2) 92(15.654,-1.6) 93(15.654,-1.2) 94(15.654,-0.8) 95(15.654,-0.4) 96(15.654,0)
  oval 0.254x1.803 smd: 33(1.627,-14.027) 34(2.027,-14.027) 35(2.427,-14.027) 36(2.827,-14.027) 37(3.227,-14.027) 38(3.627,-14.027) 39(4.027,-14.027) 40(4.427,-14.027) 41(4.827,-14.027) 42(5.227,-14.027) 43(5.627,-14.027) 44(6.027,-14.027) 45(6.427,-14.027) 46(6.827,-14.027) 47(7.227,-14.027) 48(7.627,-14.027) 49(8.027,-14.027) 50(8.427,-14.027) 51(8.827,-14.027) 52(9.227,-14.027) 53(9.627,-14.027) 54(10.027,-14.027) 55(10.427,-14.027) 56(10.827,-14.027) 57(11.227,-14.027) 58(11.627,-14.027) 59(12.027,-14.027) 60(12.427,-14.027) 61(12.827,-14.027) 62(13.227,-14.027) 63(13.627,-14.027) 64(14.027,-14.027) 97(14.027,1.627) 98(13.627,1.627) 99(13.227,1.627) 100(12.827,1.627) 101(12.427,1.627) 102(12.027,1.627) 103(11.627,1.627) 104(11.227,1.627) 105(10.827,1.627) 106(10.427,1.627) 107(10.027,1.627) 108(9.627,1.627) 109(9.227,1.627) 110(8.827,1.627) 111(8.427,1.627) 112(8.027,1.627) 113(7.627,1.627) 114(7.227,1.627) 115(6.827,1.627) 116(6.427,1.627) 117(6.027,1.627) 118(5.627,1.627) 119(5.227,1.627) 120(4.827,1.627) 121(4.427,1.627) 122(4.027,1.627) 123(3.627,1.627) 124(3.227,1.627) 125(2.827,1.627) 126(2.427,1.627) 127(2.027,1.627) 128(1.627,1.627)
L2N7002DW1T1G_SC88-6
  oval 0.406x0.508 smd: 1(0,0) 2(0.65,0) 3(1.3,0) 4(1.3,1.9) 5(0.65,1.9) 6(0,1.9)
L2N7002WT1G_SC-70-3
  oval 0.711x0.889 smd: 1(0,0) 2(-0.65,-1.9) 3(0.65,-1.9)
L03ESDL5V0CC3-2_SOT23-3
  oval 1.016x1.524 smd: 1(0,0) 2(0.965,2.083) 3(-0.965,2.083)
L03ESDL5V0CG3-2_SOT-523-3
  oval 0.406x0.787 smd: 1(0,0) 2(-0.5,-1.4) 3(0.5,-1.4)
L_5X5X3_M
  custom 0.54x0.54 smd: 1(0,0) 4(4.35,0)
  rect 0.762x0.508 smd: 2(0.699,0) 3(3.652,0)
L_5X5X3_M_2P
  rect 2.159x2.794 smd: 1(0,0) 2(4.35,0)
L_7X7X3_M
  custom 0.591x0.591 smd: 1(0,0) 4(6.05,0)
  rect 0.762x0.508 smd: 2(0.8,0) 3(5.25,0)
L_7X7X3_M_2P
  rect 2.362x3.505 smd: 1(0,0) 2(6.05,0)
LCN_DAN05-67306-0103_75P
  round 1.092 hole 1.092 unplated: (-0.75,-5.275)
  round 1.6 hole 1.6 unplated: (19.25,-5.275)
  oval 0.305x1.549 smd: 1(0,0) 2(0.25,-7.55) 3(0.5,0) 4(0.75,-7.55) 5(1,0) 6(1.25,-7.55) 7(1.5,0) 8(1.75,-7.55) 9(2,0) 10(2.25,-7.55) 11(2.5,0) 12(2.75,-7.55) 13(3,0) 14(3.25,-7.55) 15(3.5,0) 16(3.75,-7.55) 17(4,0) 18(4.25,-7.55) 19(4.5,0) 20(4.75,-7.55) 21(5,0) 22(5.25,-7.55) 23(5.5,0) 24(5.75,-7.55) 25(6,0) 26(6.25,-7.55) 27(6.5,0) 28(6.75,-7.55) 29(7,0) 30(7.25,-7.55) 31(7.5,0) 32(7.75,-7.55) 33(8,0) 34(8.25,-7.55) 35(8.5,0) 36(8.75,-7.55) 37(9,0) 38(9.25,-7.55) 39(9.5,0) 40(9.75,-7.55) 41(10,0) 42(10.25,-7.55) 43(10.5,0) 44(10.75,-7.55) 45(11,0) 46(11.25,-7.55) 47(11.5,0) 48(11.75,-7.55) 49(12,0) 50(12.25,-7.55) 51(12.5,0) 52(12.75,-7.55) 53(13,0) 54(13.25,-7.55) 55(13.5,0) 56(13.75,-7.55) 57(14,0) 58(14.25,-7.55) 67(16.5,0) 68(16.75,-7.55) 69(17,0) 70(17.25,-7.55) 71(17.5,0) 72(17.75,-7.55) 73(18,0) 74(18.25,-7.55) 75(18.5,0)
  rect 1.194x2.743 smd: 76(19.6,-0.775) 77(-1.1,-0.775)
LED_LTW-295DSKS-5A_4P
  rect 0.508x0.406 smd: 1(0,0) 2(1.2,0) 3(0,0.7) 4(1.2,0.7)
LMBT3904LT1G_SOT23-3
  oval 1.016x1.524 smd: 1(0,0) 2(0.965,2.083) 3(-0.965,2.083)
LMUN5113T1G_SOT323-3
  oval 0.711x0.889 smd: 1(0,0) 2(0.65,1.9) 3(-0.65,1.9)
LN2306LT1G_SOT23-3
  oval 1.016x1.524 smd: 1(0,0) 2(0.965,2.083) 3(-0.965,2.083)
LNG2DMTR_LGA12_2X2
  oval 0.406x0.305 smd: 1(0,0) 4(0,-1.5) 7(1.602,-1.5) 10(1.602,0)
  oval 0.508x0.305 smd: 2(0.051,-0.5) 3(0.051,-1) 8(1.551,-1) 9(1.551,-0.5)
  oval 0.305x0.508 smd: 5(0.551,-1.5) 6(1.051,-1.5) 11(1.051,0) 12(0.551,0)
LOTES_ADDR0206-P001A02_260P
  round 1.092 hole 1.092 unplated: (-67.775,-4.1)
  round 1.6 hole 1.6 unplated: (1.025,-4.1)
  oval 0.305x1.753 smd: 1(0,0) 2(-0.25,-8.2) 3(-0.5,0) 4(-0.75,-8.2) 5(-1,0) 6(-1.25,-8.2) 7(-1.5,0) 8(-1.75,-8.2) 9(-2,0) 10(-2.25,-8.2) 11(-2.5,0) 12(-2.75,-8.2) 13(-3,0) 14(-3.25,-8.2) 15(-3.5,0) 16(-3.75,-8.2) 17(-4,0) 18(-4.25,-8.2) 19(-4.5,0) 20(-4.75,-8.2) 21(-5,0) 22(-5.25,-8.2) 23(-5.5,0) 24(-5.75,-8.2) 25(-6,0) 26(-6.25,-8.2) 27(-6.5,0) 28(-6.75,-8.2) 29(-7,0) 30(-7.25,-8.2) 31(-7.5,0) 32(-7.75,-8.2) 33(-8,0) 34(-8.25,-8.2) 35(-8.5,0) 36(-8.75,-8.2) 37(-9,0) 38(-9.25,-8.2) 39(-9.5,0) 40(-9.75,-8.2) 41(-10,0) 42(-10.25,-8.2) 43(-10.5,0) 44(-10.75,-8.2) 45(-11,0) 46(-11.25,-8.2) 47(-11.5,0) 48(-11.75,-8.2) 49(-12,0) 50(-12.25,-8.2) 51(-12.5,0) 52(-12.75,-8.2) 53(-13,0) 54(-13.25,-8.2) 55(-13.5,0) 56(-13.75,-8.2) 57(-14,0) 58(-14.25,-8.2) 59(-14.5,0) 60(-14.75,-8.2) 61(-15,0) 62(-15.25,-8.2) 63(-15.5,0) 64(-15.75,-8.2) 65(-16,0) 66(-16.25,-8.2) 67(-16.5,0) 68(-16.75,-8.2) 69(-17,0) 70(-17.25,-8.2) 71(-17.5,0) 72(-17.75,-8.2) 73(-18,0) 74(-18.25,-8.2) 75(-18.5,0) 76(-18.75,-8.2) 77(-19,0) 78(-19.25,-8.2) 79(-19.5,0) 80(-19.75,-8.2) 81(-20,0) 82(-20.25,-8.2) 83(-20.5,0) 84(-20.75,-8.2) 85(-21,0) 86(-21.25,-8.2) 87(-21.5,0) 88(-21.75,-8.2) 89(-22,0) 90(-22.25,-8.2) 91(-22.5,0) 92(-22.75,-8.2) 93(-23,0) 94(-23.25,-8.2) 95(-23.5,0) 96(-23.75,-8.2) 97(-24,0) 98(-24.25,-8.2) 99(-24.5,0) 100(-24.75,-8.2) 101(-25,0) 102(-25.25,-8.2) 103(-25.5,0) 104(-25.75,-8.2) 105(-26,0) 106(-26.25,-8.2) 107(-26.5,0) 108(-26.75,-8.2) 109(-27,0) 110(-27.25,-8.2) 111(-27.5,0) 112(-27.75,-8.2) 113(-28,0) 114(-28.25,-8.2) 115(-28.5,0) 116(-28.75,-8.2) 117(-29,0) 118(-29.25,-8.2) 119(-29.5,0) 120(-29.75,-8.2) 121(-30,0) 122(-30.25,-8.2) 123(-30.5,0) 124(-30.75,-8.2) 125(-31,0) 126(-31.25,-8.2) 127(-31.5,0) 128(-31.75,-8.2) 129(-32,0) 130(-32.25,-8.2) 131(-32.5,0) 132(-32.75,-8.2) 133(-33,0) 134(-33.25,-8.2) 135(-33.5,0) 136(-33.75,-8.2) 137(-34,0) 138(-34.25,-8.2) 139(-34.5,0) 140(-34.75,-8.2) 141(-35,0) 142(-35.25,-8.2) 143(-35.5,0) 144(-35.75,-8.2) 145(-38,0) 146(-38.25,-8.2) 147(-38.5,0) 148(-38.75,-8.2) 149(-39,0) 150(-39.25,-8.2) 151(-39.5,0) 152(-39.75,-8.2) 153(-40,0) 154(-40.25,-8.2) 155(-40.5,0) 156(-40.75,-8.2) 157(-41,0) 158(-41.25,-8.2) 159(-41.5,0) 160(-41.75,-8.2) 161(-42,0) 162(-42.25,-8.2) 163(-42.5,0) 164(-42.75,-8.2) 165(-43,0) 166(-43.25,-8.2) 167(-43.5,0) 168(-43.75,-8.2) 169(-44,0) 170(-44.25,-8.2) 171(-44.5,0) 172(-44.75,-8.2) 173(-45,0) 174(-45.25,-8.2) 175(-45.5,0) 176(-45.75,-8.2) 177(-46,0) 178(-46.25,-8.2) 179(-46.5,0) 180(-46.75,-8.2) 181(-47,0) 182(-47.25,-8.2) 183(-47.5,0) 184(-47.75,-8.2) 185(-48,0) 186(-48.25,-8.2) 187(-48.5,0) 188(-48.75,-8.2) 189(-49,0) 190(-49.25,-8.2) 191(-49.5,0) 192(-49.75,-8.2) 193(-50,0) 194(-50.25,-8.2) 195(-50.5,0) 196(-50.75,-8.2) 197(-51,0) 198(-51.25,-8.2) 199(-51.5,0) 200(-51.75,-8.2) 201(-52,0) 202(-52.25,-8.2) 203(-52.5,0) 204(-52.75,-8.2) 205(-53,0) 206(-53.25,-8.2) 207(-53.5,0) 208(-53.75,-8.2) 209(-54,0) 210(-54.25,-8.2) 211(-54.5,0) 212(-54.75,-8.2) 213(-55,0) 214(-55.25,-8.2) 215(-55.5,0) 216(-55.75,-8.2) 217(-56,0) 218(-56.25,-8.2) 219(-56.5,0) 220(-56.75,-8.2) 221(-57,0) 222(-57.25,-8.2) 223(-57.5,0) 224(-57.75,-8.2) 225(-58,0) 226(-58.25,-8.2) 227(-58.5,0) 228(-58.75,-8.2) 229(-59,0) 230(-59.25,-8.2) 231(-59.5,0) 232(-59.75,-8.2) 233(-60,0) 234(-60.25,-8.2) 235(-60.5,0) 236(-60.75,-8.2) 237(-61,0) 238(-61.25,-8.2) 239(-61.5,0) 240(-61.75,-8.2) 241(-62,0) 242(-62.25,-8.2) 243(-62.5,0) 244(-62.75,-8.2) 245(-63,0) 246(-63.25,-8.2) 247(-63.5,0) 248(-63.75,-8.2) 249(-64,0) 250(-64.25,-8.2) 251(-64.5,0) 252(-64.75,-8.2) 253(-65,0) 254(-65.25,-8.2) 255(-65.5,0) 256(-65.75,-8.2) 257(-66,0) 258(-66.25,-8.2) 259(-66.5,0) 260(-66.75,-8.2)
  rect 3.505x4.597 smd: 261(-67.175,7.9) 262(0.425,7.9)
LOTES_APCI0136-P001A_75P
  round 1.092 hole 1.092 unplated: (-0.75,-5.275)
  round 1.6 hole 1.6 unplated: (19.25,-5.275)
  oval 0.305x1.549 smd: 1(0,0) 2(0.25,-7.55) 3(0.5,0) 4(0.75,-7.55) 5(1,0) 6(1.25,-7.55) 7(1.5,0) 8(1.75,-7.55) 9(2,0) 10(2.25,-7.55) 11(2.5,0) 12(2.75,-7.55) 13(3,0) 14(3.25,-7.55) 15(3.5,0) 16(3.75,-7.55) 17(4,0) 18(4.25,-7.55) 19(4.5,0) 20(4.75,-7.55) 21(5,0) 22(5.25,-7.55) 23(5.5,0) 32(7.75,-7.55) 33(8,0) 34(8.25,-7.55) 35(8.5,0) 36(8.75,-7.55) 37(9,0) 38(9.25,-7.55) 39(9.5,0) 40(9.75,-7.55) 41(10,0) 42(10.25,-7.55) 43(10.5,0) 44(10.75,-7.55) 45(11,0) 46(11.25,-7.55) 47(11.5,0) 48(11.75,-7.55) 49(12,0) 50(12.25,-7.55) 51(12.5,0) 52(12.75,-7.55) 53(13,0) 54(13.25,-7.55) 55(13.5,0) 56(13.75,-7.55) 57(14,0) 58(14.25,-7.55) 59(14.5,0) 60(14.75,-7.55) 61(15,0) 62(15.25,-7.55) 63(15.5,0) 64(15.75,-7.55) 65(16,0) 66(16.25,-7.55) 67(16.5,0) 68(16.75,-7.55) 69(17,0) 70(17.25,-7.55) 71(17.5,0) 72(17.75,-7.55) 73(18,0) 74(18.25,-7.55) 75(18.5,0)
  rect 1.194x2.743 smd: 76(-1.1,-0.775) 77(19.6,-0.775)
LRB715FT1G_SOT323-3
  oval 0.711x0.889 smd: 1(0,0) 2(0.65,1.9) 3(-0.65,1.9)
LTC015EUBFS8TL_UMT3F
  oval 0.787x0.889 smd: 1(0,0) 2(-0.65,-1.6) 3(0.65,-1.6)
MESS138W-G_SOT323-3
  oval 0.711x0.889 smd: 1(0,0) 2(-0.65,-1.9) 3(0.65,-1.9)
MMST3904-7-F_SOT323-3
  oval 0.711x0.889 smd: 1(0,0) 2(0.65,1.9) 3(-0.65,1.9)
MURAT_BLM15AG102SN1D_2P
  rect 0.457x0.508 smd: 1(0,0) 2(0.85,0)
MURAT_BLM15BD121SN1D_2P
  rect 0.457x0.508 smd: 1(0,0) 2(0.85,0)
MURAT_BLM15PD600SN1D_2P
  rect 0.508x0.762 smd: 1(0,0) 2(0.75,0)
MURAT_BLM15PX221SN1D_2P
  rect 0.457x0.508 smd: 1(0,0) 2(0.85,0)
MURAT_BLM15PX330SN1D_2P
  rect 0.457x0.508 smd: 1(0,0) 2(0.85,0)
NCT7718W_MSOP8
  oval 0.381x1.575 smd: 1(0,0) 2(0.65,0) 3(1.3,0) 4(1.95,0) 5(1.95,4.35) 6(1.3,4.35) 7(0.65,4.35) 8(0,4.35)
PJSOT24C_SOT23-3
  oval 1.016x1.524 smd: 1(0,0) 2(0.965,2.083) 3(-0.965,2.083)
Q_N_DFN56-8-5
  oval 0.61x1.27 smd: 1(0,0) 2(1.27,0) 3(2.54,0) 4(3.81,0)
  custom 1.105x1.105 smd: 5(1.905,3.715)
R0201_0OHM
  rect 0.381x0.356 smd: 1(0,0) 2(0.584,0)
R0402_0OHM
  rect 0.508x0.559 smd: 1(0,0) 2(0.914,0)
R0603_0OHM
  rect 0.635x0.889 smd: 1(0,0) 2(1.397,0)
R0805_0OHM
  rect 0.813x1.397 smd: 1(0,0) 2(1.702,0)
R_0201
  rect 0.381x0.356 smd: 1(0,0) 2(0.584,0)
R_0402
  rect 0.508x0.559 smd: 1(0,0) 2(0.914,0)
R_0402-NPM
  rect 0.508x0.559 smd: 1(0,0) 2(0.914,0)
R_0603
  rect 0.635x0.889 smd: 1(0,0) 2(1.397,0)
R_0805
  rect 0.813x1.397 smd: 1(0,0) 2(1.702,0)
R_1206
  rect 1.016x1.651 smd: 1(0,0) 2(2.667,0)
R_1206_4P-D
  custom 0.371x0.371 smd: 1(0,0) 4(3.327,0)
  custom 0.114x0.114 smd: 2(0.775,0) 3(2.553,0)
R_1206_4P-D-NPM
  custom 0.371x0.371 smd: 1(0,0) 4(3.327,0)
  custom 0.114x0.114 smd: 2(0.775,0) 3(2.553,0)
RB551V-30_SOD323-2
  rect 0.559x0.813 smd: 1(0,0) 2(2.3,0)
RB751S40T1G_SOD523-2
  rect 0.61x0.787 smd: 1(0,0) 2(1.7,0)
RB751V-40_SOD323-2
  rect 0.787x0.889 smd: 1(0,0) 2(2.14,0)
RT3601EAGQW_WQFN28_4X4
  oval 0.889x0.203 smd: 1(0,0) 2(0,-0.4) 3(0,-0.8) 4(0,-1.2) 5(0,-1.6) 6(0,-2) 7(0,-2.4) 15(4.1,-2.4) 16(4.1,-2) 17(4.1,-1.6) 18(4.1,-1.2) 19(4.1,-0.8) 20(4.1,-0.4) 21(4.1,0)
  oval 0.203x0.889 smd: 8(0.85,-3.25) 9(1.25,-3.25) 10(1.65,-3.25) 11(2.05,-3.25) 12(2.45,-3.25) 13(2.85,-3.25) 14(3.25,-3.25) 22(3.25,0.85) 23(2.85,0.85) 24(2.45,0.85) 25(2.05,0.85) 26(1.65,0.85) 27(1.25,0.85) 28(0.85,0.85)
  rect 2.388x2.388 smd: 29(2.05,-1.2)
RT6226AGQUF_UQFN12_3X3
  oval 0.838x0.254 smd: 1(0,0) 6(3.15,0)
  oval 1.397x0.254 smd: 2(0.275,-0.72) 3(0.275,-1.62)
  oval 2.337x0.254 smd: 4(2.41,-1.17) 5(2.41,-0.45)
  oval 0.254x0.838 smd: 7(2.7,0.955) 8(2.25,0.955) 9(1.8,0.955) 10(1.35,0.955) 11(0.9,0.955) 12(0.45,0.955)
RT8061AZQW_WDFN10_3X3
  oval 0.254x0.889 smd: 1(0,0) 2(0.5,0) 3(1,0) 4(1.5,0) 5(2,0) 6(2,3.1) 7(1.5,3.1) 8(1,3.1) 9(0.5,3.1) 10(0,3.1)
  rect 2.464x1.626 smd: 11(1,1.55)
RT8207PGQW_WQFN20_3X3
  oval 0.203x0.889 smd: 1(0,0) 2(0.4,0) 3(0.8,0) 4(1.2,0) 5(1.6,0) 11(1.6,3.1) 12(1.2,3.1) 13(0.8,3.1) 14(0.4,3.1) 15(0,3.1)
  oval 0.889x0.203 smd: 6(2.35,0.75) 7(2.35,1.15) 8(2.35,1.55) 9(2.35,1.95) 10(2.35,2.35) 16(-0.75,2.35) 17(-0.75,1.95) 18(-0.75,1.55) 19(-0.75,1.15) 20(-0.75,0.75)
  rect 1.702x1.702 smd: 21(0.8,1.55)
RT9059GSP_SO8
  oval 0.635x1.854 smd: 1(0,0) 2(1.27,0) 3(2.54,0) 4(3.81,0) 5(3.81,5.157) 6(2.54,5.157) 7(1.27,5.157) 8(0,5.157)
  rect 2.311x2.311 smd: 9(1.905,2.579)
RTL8106E-CG_QFN32_4X4
  oval 0.203x0.838 smd: 1(0,0) 2(0.4,0) 3(0.8,0) 4(1.2,0) 5(1.6,0) 6(2,0) 7(2.4,0) 8(2.8,0) 17(2.8,4.15) 18(2.4,4.15) 19(2,4.15) 20(1.6,4.15) 21(1.2,4.15) 22(0.8,4.15) 23(0.4,4.15) 24(0,4.15)
  oval 0.838x0.203 smd: 9(3.475,0.675) 10(3.475,1.075) 11(3.475,1.475) 12(3.475,1.875) 13(3.475,2.275) 14(3.475,2.675) 15(3.475,3.075) 16(3.475,3.475) 25(-0.675,3.475) 26(-0.675,3.075) 27(-0.675,2.675) 28(-0.675,2.275) 29(-0.675,1.875) 30(-0.675,1.475) 31(-0.675,1.075) 32(-0.675,0.675)
  rect 2.692x2.692 smd: 33(1.4,2.075)
RUM002N02GT2L_VMT3
  oval 0.508x0.457 smd: 1(0,0)
  oval 0.406x0.457 smd: 2(-0.4,-1.15) 3(0.4,-1.15)
SHORTPADS
  custom 0.19x0.19 smd: 1(-0.483,0) 2(0.483,0)
SINGA_2RJ3076-078211F_8P-T
  round 1.295 hole 0.889: 1(0,0) 2(-1.02,1.1) 3(-2.04,0) 4(-3.06,1.1) 5(-4.08,0) 6(-5.1,1.1) 7(-6.12,0) 8(-7.14,1.1)
  oval 0.991x2.007 hole 0.61x1.6: 9(4.83,-2.3) 10(4.83,-10.1) 11(-11.97,-10.1) 12(-11.97,-2.3)
SN74LVC1G07DCKR_SC70-5
  oval 0.381x0.864 smd: 1(0,0) 2(0.65,0) 3(1.3,0) 4(1.3,1.74) 5(0,1.74)
SW_TST71-N-220-T170-S017_2P
  rect 0.61x1.499 smd: 1(0,0) 2(3.2,0)
SY6288C20AAC_SOT23-5
  oval 0.559x0.787 smd: 1(0,0) 2(0.95,0) 3(1.9,0) 4(1.9,2.4) 5(0,2.4)
SY6288D20AAC_SOT23-5
  oval 0.559x0.787 smd: 1(0,0) 2(0.95,0) 3(1.9,0) 4(1.9,2.4) 5(0,2.4)
SY8286BRAC_QFN20_3X3
  oval 0.889x0.254 smd: 1(0,0) 2(0,-0.45) 3(0,-0.9) 4(0,-1.35) 5(0,-1.8) 11(3.1,-1.8) 12(3.1,-1.35) 13(3.1,-0.9) 14(3.1,-0.45) 15(3.1,0)
  oval 0.254x0.889 smd: 6(0.65,-2.45) 7(1.1,-2.45) 8(1.55,-2.45) 9(2,-2.45) 10(2.45,-2.45) 16(2.45,0.65) 17(2,0.65) 18(1.55,0.65) 19(1.1,0.65) 20(0.65,0.65)
  rect 0.991x0.991 smd: 21(1.55,-0.9)
SY8288CRAC_QFN20_3X3
  oval 0.889x0.254 smd: 1(0,0) 2(0,-0.45) 3(0,-0.9) 4(0,-1.35) 5(0,-1.8) 11(3.1,-1.8) 12(3.1,-1.35) 13(3.1,-0.9) 14(3.1,-0.45) 15(3.1,0)
  oval 0.254x0.889 smd: 6(0.65,-2.45) 7(1.1,-2.45) 8(1.55,-2.45) 9(2,-2.45) 10(2.45,-2.45) 16(2.45,0.65) 17(2,0.65) 18(1.55,0.65) 19(1.1,0.65) 20(0.65,0.65)
  rect 0.991x0.991 smd: 21(1.55,-0.9)
TC7SH08FUF_SSOP5
  oval 0.457x0.711 smd: 1(0,0) 2(0.65,0) 3(1.3,0) 4(1.3,1.875) 5(0,1.875)
THGBMBG8D4KBAIRNHDI_VFBGA_153P
  round 0.229 smd: A1(0,0) A2(0.5,0) A3(1,0) A4(1.5,0) A5(2.001,0) A6(2.501,0) A7(3.001,0) A8(3.501,0) A9(4.001,0) A10(4.501,0) A11(5.001,0) A12(5.501,0) A13(6.002,0) A14(6.502,0) B1(0,-0.5) B2(0.5,-0.5) B3(1,-0.5) B4(1.5,-0.5) B5(2.001,-0.5) B6(2.501,-0.5) B7(3.001,-0.5) B8(3.501,-0.5) B9(4.001,-0.5) B10(4.501,-0.5) B11(5.001,-0.5) B12(5.501,-0.5) B13(6.002,-0.5) B14(6.502,-0.5) C1(0,-1) C2(0.5,-1) C3(1,-1) C4(1.5,-1) C5(2.001,-1) C6(2.501,-1) C7(3.001,-1) C8(3.501,-1) C9(4.001,-1) C10(4.501,-1) C11(5.001,-1) C12(5.501,-1) C13(6.002,-1) C14(6.502,-1) D1(0,-1.5) D2(0.5,-1.5) D3(1,-1.5) D4(1.5,-1.5) D12(5.501,-1.5) D13(6.002,-1.5) D14(6.502,-1.5) E1(0,-2.001) E2(0.5,-2.001) E3(1,-2.001) E5(2.001,-2.001) E6(2.501,-2.001) E7(3.001,-2.001) E8(3.501,-2.001) E9(4.001,-2.001) E10(4.501,-2.001) E12(5.501,-2.001) E13(6.002,-2.001) E14(6.502,-2.001) F1(0,-2.501) F2(0.5,-2.501) F3(1,-2.501) F5(2.001,-2.501) F10(4.501,-2.501) F12(5.501,-2.501) F13(6.002,-2.501) F14(6.502,-2.501) G1(0,-3.001) G2(0.5,-3.001) G3(1,-3.001) G5(2.001,-3.001) G10(4.501,-3.001) G12(5.501,-3.001) G13(6.002,-3.001) G14(6.502,-3.001) H1(0,-3.501) H2(0.5,-3.501) H3(1,-3.501) H5(2.001,-3.501) H10(4.501,-3.501) H12(5.501,-3.501) H13(6.002,-3.501) H14(6.502,-3.501) J1(0,-4.001) J2(0.5,-4.001) J3(1,-4.001) J5(2.001,-4.001) J10(4.501,-4.001) J12(5.501,-4.001) J13(6.002,-4.001) J14(6.502,-4.001) K1(0,-4.501) K2(0.5,-4.501) K3(1,-4.501) K5(2.001,-4.501) K6(2.501,-4.501) K7(3.001,-4.501) K8(3.501,-4.501) K9(4.001,-4.501) K10(4.501,-4.501) K12(5.501,-4.501) K13(6.002,-4.501) K14(6.502,-4.501) L1(0,-5.001) L2(0.5,-5.001) L3(1,-5.001) L12(5.501,-5.001) L13(6.002,-5.001) L14(6.502,-5.001) M1(0,-5.501) M2(0.5,-5.501) M3(1,-5.501) M4(1.5,-5.501) M5(2.001,-5.501) M6(2.501,-5.501) M7(3.001,-5.501) M8(3.501,-5.501) M9(4.001,-5.501) M10(4.501,-5.501) M11(5.001,-5.501) M12(5.501,-5.501) M13(6.002,-5.501) M14(6.502,-5.501) N1(0,-6.002) N2(0.5,-6.002) N3(1,-6.002) N4(1.5,-6.002) N5(2.001,-6.002) N6(2.501,-6.002) N7(3.001,-6.002) N8(3.501,-6.002) N9(4.001,-6.002) N10(4.501,-6.002) N11(5.001,-6.002) N12(5.501,-6.002) N13(6.002,-6.002) N14(6.502,-6.002) P1(0,-6.502) P2(0.5,-6.502) P3(1,-6.502) P4(1.5,-6.502) P5(2.001,-6.502) P6(2.501,-6.502) P7(3.001,-6.502) P8(3.501,-6.502) P9(4.001,-6.502) P10(4.501,-6.502) P11(5.001,-6.502) P12(5.501,-6.502) P13(6.002,-6.502) P14(6.502,-6.502)
TPC12
  round 0.305 smd: 1(0,0)
TPS22966DPUR_SON14_2X3-S
  oval 0.254x0.813 smd: 1(0,0) 2(0.4,0) 6(2,0) 7(2.4,0) 8(2.4,2.05) 9(2,2.05) 13(0.4,2.05) 14(0,2.05)
  oval 0.203x0.762 smd: 3(0.8,0) 4(1.2,0) 5(1.6,0) 10(1.6,2.05) 11(1.2,2.05) 12(0.8,2.05)
  rect 2.489x0.889 smd: 15(1.2,1.025)
TVNST52302AB0_SOT523-3
  oval 0.508x0.559 smd: 1(0,0) 2(-0.5,-1.4) 3(0.5,-1.4)
X_7XZ3200003_4P
  rect 1.397x1.194 smd: 1(0,0) 2(2.2,0) 3(2.2,1.7) 4(0,1.7)
Y_7M19200019_4P
  rect 1.397x1.194 smd: 1(0,0) 2(2.2,0) 3(2.2,1.7) 4(0,1.7)
Y_7V25000014_4P
  rect 1.397x1.194 smd: 1(0,0) 2(2.2,0) 3(2.2,1.7) 4(0,1.7)
Y_9H03200031_2P
  rect 0.991x1.803 smd: 1(0,0) 2(2.5,0)
YUQIU_PJ753-F07J1BE-B_7P-T
  oval 0.991x1.803 hole 0.61x1.397: 1(0,0) 2(9.5,-5.5) 3(9.5,-8.6) 4(0,-7.8) 5(9.5,0) 6(9.5,-2.75) 7(0,-2.65)

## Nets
1.8V_PRIM_EN: PR1808.1 UE1.90
3.3V_TS_EN: R72.1 R5220.2 U14.4
3VS_ON: C980.2 R927.1 U11.5
5VS_ON: C979.2 R926.2 U11.3
+0.6V_DDR_VTT: CD5.1 CD6.1 CD7.1 CD8.1 DD1.2 JDIMM1.258 PJPM03.2
+0.6V_M0_VREFDQ: T3.1(TP-1) UC1.AY31
+0.6V_M1_VREFDQ: T4.1(TP-1) UC1.AY25
+0.6VSP: PCM20.1 PJPM03.1 PUM01.2 PUM01.20
+1.2V_DDR: CD11.1 CD12.1 CD13.1 CD14.1 CD15.1 CD16.1 CD17.1 CD18.1 CD19.1 CD20.1 CD21.1 CD22.1 CD23.1 CD24.1 CD25.1 CD26.1 CD27.1 CD31.1 CD32.1 CD33.1 DC6.2 JDIMM1.12 JDIMM1.33 JDIMM1.54 JDIMM1.75 JDIMM1.96 JDIMM1.111 JDIMM1.112 JDIMM1.117 JDIMM1.118 JDIMM1.123 JDIMM1.124 JDIMM1.129 JDIMM1.130 JDIMM1.135 JDIMM1.136 JDIMM1.141 JDIMM1.142 JDIMM1.147 JDIMM1.148 JDIMM1.153 JDIMM1.154 JDIMM1.159 JDIMM1.160 JDIMM1.163 JDIMM1.178 JDIMM1.199 JDIMM1.220 JDIMM1.241 JP12.1 PJPM02.2 RC41.1 RD10.1 RD23.1 RD37.1
+1.2V_DDR_SOC: CC60.2 CC61.2 CC62.2 CC63.2 CC64.2 CC65.2 CC66.2 CC67.2 CC68.2 CC69.2 CC70.2 CC71.2 CC73.2 CC272.2 JP12.2 UC1.AP18 UC1.AP21 UC1.AP36 UC1.AP38 UC1.AT18 UC1.AT20 UC1.AT21 UC1.AT35 UC1.AT36 UC1.AT38 UC1.BA13 UC1.BA15 UC1.BA25 UC1.BA31 UC1.BA41 UC1.BA43
+1.2V_DSI: CC28.2 RC131.2 UC1.AW12
+1.2V_GLML: CC42.2 CC43.2 CC44.2 CC45.2 CC46.1 RC126.2 UC1.AL36 UC1.AL38 UC1.AM20 UC1.AP20
+1.2V_MPHY: CC23.2 CC24.2 CC25.2 CC26.2 RC129.2 UC1.AC21 UC1.AE20 UC1.AE21 UC1.AF20 UC1.AF21
+1.2V_PLL: CC47.2 CC48.2 CC49.2 CC50.1 CC51.1 CC52.1 RC127.2 UC1.AL18 UC1.AM18
+1.2V_SOC: RC125.2 RC126.1 RC127.1 RC128.1 RC129.1 RC130.1 RC131.1
+1.2V_USB2: CC27.2 RC128.2 UC1.AG18 UC1.AJ20
+1.2V_VNNAON: RC130.2 UC1.AA18 UC1.AA20
+1.2VP: PCM05.1 PCM06.1 PCM07.1 PCM08.1 PCM09.1 PCM10.1 PCM17.2 PCM18.1 PJPM02.1 PLM01.1 PRM10.2 PUM01.5 PUM01.19
+1.05VS: PCG09.1 PCZ03.1 PJPH02.2 PRG04.1 PRG05.1 PRZ05.1 PRZ06.1 RC59.1 RC61.1 RC132.1 RC133.1 RC134.1 RC135.1 RC136.1
+1.05VS_SOC_FHV0: RC134.2 UC1.AG51
+1.05VS_SOC_FHV1: RC136.2 UC1.AG49
+1.05VS_SOC_FUSE: RC135.2 UC1.AJ51
+1.05VS_SOC_SRAM: CC35.2 CC36.2 CC37.2 CC38.1 CC74.2 CC75.2 CC76.2 CC77.2 CC78.2 CC79.2 RC132.2 UC1.AA36 UC1.AA38 UC1.AC33 UC1.AC35 UC1.AC36 UC1.AC38 UC1.AE33 UC1.AE35 UC1.AE36 UC1.AE38 UC1.AF27 UC1.AF28 UC1.AF36 UC1.AF38 UC1.Y36 UC1.Y38
+1.05VSP: PCH05.1 PCH06.1 PCH07.1 PCH08.1 PCH14.1 PJPH02.1 PLH01.2 PRH08.2
+1.8V_AVDD: CA495.2 RA35.2 UA1.33
+1.8V_CPVDD: CA46.1 CA50.1 CA484.2 CA492.1 RA36.2 UA1.29
+1.8V_DVDDIO: CA477.1 CA490.1 RA65.2 UA1.8
+1.8V_EMMC: CM3.1 CM4.1 CM10.1 RM2.2 RM33.2 UM1.C6 UM1.M4 UM1.N4 UM1.P3 UM1.P5
+1.8V_PRIM: CC96.2 PJP1802.2 PRG25.1 PRZ20.1 QA2.1 RC6.1 RC7.1 RC8.2 RC9.2 RC30.2 RC31.2 RC32.2 RC34.1 RC69.2 RC70.2 RC79.1 RC80.1 RC87.1 RC88.1 RC93.1 RC95.2 RC97.2 RC99.2 RC101.2 RC104.2 RC106.2 RC109.1 RC110.1 RC111.2 RC112.2 RC113.2 RC114.1 RC123.1 RC140.1 RC141.1 RC155.2 RC156.1 RC171.1 RC173.1 RE13.1 RM2.1 RM27.1 RT28.2 RW7.2 RW8.2 RW22.2 RW23.2 UC8.5 UC12.5 UM3.6 UM3.7
+1.8VALW_SOC: CC53.2 CC54.2 CC55.2 CC56.2 CC57.2 CC58.1 CC59.2 RC123.2 UC1.AG23 UC1.AJ23 UC1.T21 UC1.T23 UC1.T25 UC1.V21 UC1.V23 UC1.V25
+1.8VALWP: PC1802.1 PC1803.1 PC1804.1 PC1807.1 PJP1802.1 PL1801.2 PR1807.1
